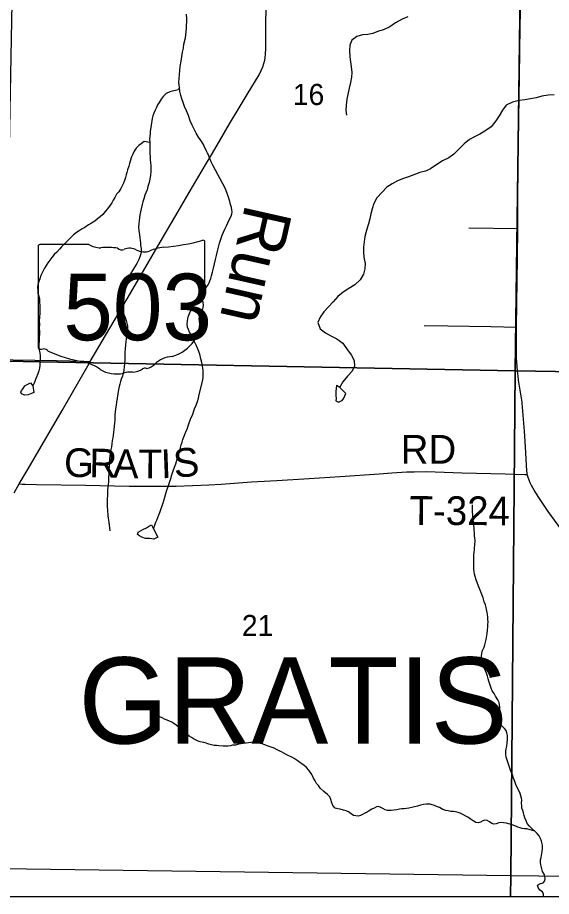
# Model space of a CAD drawing. Extents: x 0 to 34, y 0 to 22.
# Drawn here: x 5.468 to 6.524, y 14.1 to 15.838 of the extents above; entities that cross this region are included whole.
import ezdxf

# ---------------------------------------------------------------- set-up
doc = ezdxf.new("R2010")
doc.units = 0
for name, color, linetype in [('GM_X_Corporation', 7, 'Continuous'), ('GM_X_Minor_River', 7, 'Continuous'), ('GM_X_Minor_River_Text', 7, 'Continuous'), ('GM_X_Section_Text', 7, 'Continuous'), ('GM_X_State_Location', 7, 'Continuous'), ('GM_X_State_Route', 7, 'Continuous'), ('GM_X_State_Shield', 7, 'Continuous'), ('GM_X_Township_Road', 7, 'Continuous'), ('GM_X_Township_Road_Text', 7, 'Continuous'), ('GM_X_Township_Text', 7, 'Continuous'), ('SH_Data', 7, 'Continuous')]:
    doc.layers.add(name, color=color, linetype=linetype)

msp = doc.modelspace()

# ---------------------------------------------------------------- linework, layer by layer
at = {"layer": 'GM_X_Corporation'}
msp.add_lwpolyline([(3.4754, 17.1134), (3.4672, 16.2781), (3.4601, 16.0804), (3.4533, 15.0461), (3.4516, 14.7743), (3.448, 14.3179), (3.4463, 14.1), (8.9, 14.1)], dxfattribs=at)
for points in [[(5.4651, 16.258), (6.4674, 16.2404), (6.4527, 15.1394), (5.4447, 15.1591)], [(6.4674, 16.2404), (7.4675, 16.2282), (7.4535, 15.1233), (6.4527, 15.1394)], [(5.4447, 15.1591), (6.4527, 15.1394), (6.4438, 14.1407), (5.4377, 14.1543)], [(6.4527, 15.1394), (7.4535, 15.1233), (7.4459, 14.1288), (6.4438, 14.1407)], [(5.4372, 14.1), (6.4436, 14.1), (6.4438, 14.1407), (5.4377, 14.1543)], [(6.4436, 14.1), (7.4457, 14.1), (7.4459, 14.1288), (6.4438, 14.1407)]]:
    msp.add_lwpolyline(points, close=True, dxfattribs=at)
at = {"layer": 'GM_X_Minor_River'}
for points in [[(5.8826, 15.4922), (5.8787, 15.5011), (5.8647, 15.5277), (5.8597, 15.5366), (5.855, 15.5451), (5.8511, 15.5532), (5.8479, 15.5609), (5.8458, 15.5666), (5.8441, 15.5701), (5.8426, 15.5728), (5.8412, 15.5759), (5.8391, 15.5809), (5.8359, 15.5871), (5.8315, 15.5948), (5.8265, 15.6022), (5.8218, 15.6099), (5.8175, 15.6176), (5.8135, 15.6254), (5.8096, 15.6342), (5.8062, 15.6446), (5.8023, 15.6542), (5.7988, 15.6623), (5.796, 15.6703), (5.7936, 15.6776), (5.7911, 15.6845), (5.7895, 15.6922), (5.7886, 15.7006), (5.7877, 15.7101), (5.7898, 15.7416), (5.7917, 15.7521), (5.7935, 15.7612), (5.7949, 15.7703), (5.7963, 15.7782), (5.7976, 15.7858), (5.8003, 15.7986), (5.8012, 15.8046), (5.8024, 15.8168), (5.8026, 15.8232), (5.8031, 15.8293), (5.8029, 15.835), (5.8025, 15.8449)], [(6.2403, 15.8402), (6.2292, 15.8356), (6.2157, 15.828), (6.2045, 15.82), (6.1922, 15.8142), (6.1822, 15.8115), (6.1711, 15.8069), (6.1612, 15.8052), (6.1505, 15.804), (6.1394, 15.8013), (6.1294, 15.794), (6.1253, 15.7838), (6.1246, 15.7732), (6.1254, 15.761), (6.127, 15.7507), (6.1282, 15.7408), (6.1294, 15.7301), (6.1288, 15.7203), (6.1266, 15.7101), (6.124, 15.6987), (6.1196, 15.6768), (6.1185, 15.6655), (6.1178, 15.6556), (6.1187, 15.6457)], [(5.7886, 15.7006), (5.7862, 15.6957), (5.7805, 15.6944), (5.7744, 15.6926), (5.7694, 15.6913), (5.7621, 15.6884), (5.7562, 15.6825), (5.7527, 15.6773), (5.7487, 15.6706), (5.7455, 15.6657), (5.7431, 15.6605), (5.7407, 15.6556), (5.7382, 15.6492), (5.7362, 15.6439), (5.7349, 15.6387), (5.7326, 15.6254), (5.7308, 15.6133), (5.7306, 15.6084), (5.7296, 15.5985), (5.7298, 15.5913), (5.73, 15.586), (5.7298, 15.581), (5.7301, 15.5757), (5.7299, 15.5693), (5.7305, 15.5635), (5.7307, 15.5575), (5.7313, 15.5514), (5.7319, 15.546), (5.7321, 15.5407), (5.732, 15.535), (5.7313, 15.5259), (5.7287, 15.5123), (5.7262, 15.5044), (5.7245, 15.498), (5.7224, 15.492), (5.7203, 15.4871), (5.7179, 15.4796), (5.7162, 15.4739), (5.7149, 15.469), (5.7131, 15.4603), (5.7105, 15.4482), (5.7096, 15.4422), (5.7087, 15.4361), (5.7081, 15.4308), (5.7079, 15.4236), (5.7081, 15.4175), (5.7094, 15.4087), (5.71, 15.4026), (5.7106, 15.3977), (5.7116, 15.3927), (5.7118, 15.3874), (5.7132, 15.3816), (5.713, 15.376), (5.7121, 15.371), (5.7104, 15.3654), (5.7084, 15.3597), (5.7044, 15.3523), (5.7008, 15.3467), (5.6976, 15.3414), (5.692, 15.3317), (5.6884, 15.3257), (5.6856, 15.3186), (5.6839, 15.3137), (5.6826, 15.3069), (5.6813, 15.3005), (5.6804, 15.2956), (5.6783, 15.2892), (5.6766, 15.2835), (5.675, 15.2782), (5.6744, 15.2729), (5.6739, 15.2669), (5.6745, 15.2611), (5.6759, 15.2562), (5.6787, 15.2508), (5.6812, 15.2454), (5.6833, 15.2389), (5.6847, 15.2339), (5.6857, 15.2285), (5.6859, 15.2213), (5.6853, 15.2149), (5.6843, 15.2077), (5.6831, 15.2028), (5.6825, 15.1978)], [(6.53, 15.6854), (6.5178, 15.685), (6.5056, 15.6831), (6.4938, 15.68), (6.4827, 15.678), (6.4716, 15.6757), (6.4602, 15.6741), (6.4472, 15.671), (6.4349, 15.6653), (6.4274, 15.6552), (6.4207, 15.6444), (6.4143, 15.6343), (6.4053, 15.6224), (6.3929, 15.6137), (6.3828, 15.6079), (6.3721, 15.6025), (6.3621, 15.5974), (6.3519, 15.589), (6.341, 15.5779), (6.3313, 15.5683), (6.3212, 15.5613), (6.3089, 15.5548), (6.2977, 15.5476), (6.2853, 15.5395), (6.2753, 15.5349), (6.2638, 15.5318), (6.2523, 15.5276), (6.2419, 15.5233), (6.232, 15.5202), (6.2201, 15.5152), (6.2093, 15.5098), (6.1989, 15.5032), (6.1895, 15.4929), (6.1793, 15.4821)], [(5.7298, 15.5913), (5.7188, 15.5931), (5.713, 15.5884), (5.708, 15.5851), (5.7033, 15.5799), (5.6993, 15.5743), (5.6961, 15.5683), (5.694, 15.5627), (5.6911, 15.5544), (5.6895, 15.5495), (5.6882, 15.5446), (5.6861, 15.5374), (5.6848, 15.5322), (5.6835, 15.5273), (5.6819, 15.5224), (5.6798, 15.5163), (5.6778, 15.5107), (5.6753, 15.5055), (5.6725, 15.5002), (5.6689, 15.4939), (5.6642, 15.489), (5.6606, 15.4823), (5.6575, 15.4775), (5.6547, 15.4722), (5.6515, 15.4674), (5.646, 15.4603), (5.6416, 15.4547), (5.6369, 15.4488), (5.6315, 15.4444), (5.6264, 15.4403), (5.621, 15.4359), (5.6144, 15.4319), (5.609, 15.4283), (5.6013, 15.4232), (5.5959, 15.4207), (5.5905, 15.4163), (5.5851, 15.413), (5.5792, 15.4086), (5.5738, 15.4031), (5.5664, 15.3964), (5.5609, 15.3905), (5.5551, 15.385), (5.5511, 15.3801), (5.5464, 15.3746), (5.541, 15.3698), (5.5359, 15.3639), (5.5323, 15.3583), (5.5284, 15.3534), (5.5248, 15.3478), (5.522, 15.343), (5.518, 15.3347)], [(5.7374, 14.8272), (5.738, 14.8288), (5.7397, 14.8341), (5.7417, 14.8401), (5.7438, 14.8442), (5.7479, 14.8547), (5.7495, 14.8596), (5.7516, 14.8656), (5.7541, 14.8724), (5.7562, 14.8788), (5.7587, 14.8852), (5.7633, 14.9017), (5.7663, 14.9111), (5.7692, 14.919), (5.7717, 14.9265), (5.7738, 14.9341), (5.7763, 14.942), (5.7788, 14.9491), (5.7813, 14.9555), (5.7847, 14.9676), (5.7868, 14.9739), (5.7881, 14.9792), (5.7897, 14.9837), (5.7906, 14.9883), (5.7919, 14.9932), (5.794, 14.9984), (5.7956, 15.0041), (5.7977, 15.0101), (5.8002, 15.0157), (5.8043, 15.0262), (5.8059, 15.0311), (5.808, 15.0367), (5.8121, 15.0472), (5.8142, 15.0521), (5.8187, 15.0645), (5.8216, 15.0717), (5.8241, 15.0788), (5.8262, 15.0859), (5.8279, 15.0931), (5.8327, 15.1131), (5.834, 15.1195), (5.8354, 15.1263), (5.8356, 15.1335), (5.8355, 15.1411), (5.8345, 15.1487), (5.8329, 15.156), (5.8312, 15.1637), (5.8288, 15.1725), (5.8257, 15.1809), (5.8225, 15.189), (5.8193, 15.1959), (5.8165, 15.2013), (5.8115, 15.2114), (5.8086, 15.216), (5.8065, 15.2214), (5.8047, 15.226), (5.8041, 15.2317), (5.8047, 15.2385), (5.8061, 15.2465), (5.8086, 15.2532), (5.811, 15.2589), (5.8139, 15.2649), (5.8171, 15.2705), (5.8206, 15.2757), (5.8242, 15.2813), (5.8282, 15.2861), (5.8321, 15.2901), (5.8352, 15.2942), (5.8384, 15.2987), (5.8416, 15.3043), (5.8452, 15.3095), (5.8472, 15.314), (5.8488, 15.3177), (5.8505, 15.3222), (5.8522, 15.3279), (5.8539, 15.3347), (5.856, 15.3426), (5.8582, 15.3513), (5.86, 15.3596), (5.8621, 15.3679), (5.8639, 15.3762), (5.8681, 15.392), (5.8703, 15.4003), (5.8732, 15.4078), (5.876, 15.4141), (5.8785, 15.4202), (5.8817, 15.4265), (5.8845, 15.4325), (5.8878, 15.4396), (5.891, 15.4456), (5.8923, 15.4505), (5.8928, 15.4539), (5.8925, 15.4581), (5.8915, 15.4627), (5.8898, 15.4684), (5.8881, 15.4749), (5.8857, 15.4834), (5.8826, 15.4922)], [(6.1793, 15.4821), (6.1729, 15.4705), (6.1696, 15.4604), (6.167, 15.4505), (6.1652, 15.4403), (6.1627, 15.4305), (6.1593, 15.4196), (6.1555, 15.4057), (6.1537, 15.3947), (6.1523, 15.3845), (6.1524, 15.3746), (6.1536, 15.3643), (6.1559, 15.3521), (6.1552, 15.3411), (6.1526, 15.3309), (6.1462, 15.3197), (6.1357, 15.3101), (6.1234, 15.3024), (6.1122, 15.2952), (6.1017, 15.2867), (6.0927, 15.2763), (6.0833, 15.2663), (6.0743, 15.2563), (6.0668, 15.2459), (6.0623, 15.2354), (6.0672, 15.2227), (6.0772, 15.2148), (6.0881, 15.2092), (6.0997, 15.2028), (6.1116, 15.1941), (6.1203, 15.1821), (6.1287, 15.1708), (6.1341, 15.1596), (6.135, 15.149), (6.1305, 15.1392), (6.1211, 15.1288), (6.1117, 15.1177), (6.1061, 15.1076), (6.1058, 15.1067)], [(5.518, 15.3347), (5.5144, 15.3284), (5.5123, 15.3216), (5.5102, 15.3163), (5.5085, 15.3103), (5.5076, 15.305), (5.5082, 15.2985), (5.5084, 15.2932), (5.5102, 15.2874), (5.5115, 15.2817), (5.5121, 15.2756), (5.5127, 15.2691), (5.5128, 15.2608), (5.5123, 15.2543), (5.5116, 15.2452), (5.5114, 15.2388), (5.5116, 15.2315), (5.5114, 15.2247), (5.5116, 15.2163), (5.5108, 15.1883), (5.5113, 15.1803), (5.5123, 15.1753), (5.5129, 15.1696), (5.513, 15.1616), (5.5125, 15.1563), (5.5124, 15.1506), (5.5118, 15.1449), (5.5105, 15.1396), (5.5088, 15.1336), (5.5052, 15.1261), (5.5035, 15.1208), (5.5003, 15.1137), (5.4984, 15.1099)], [(5.6825, 15.1978), (5.6819, 15.1903), (5.6814, 15.183), (5.6808, 15.1766), (5.6806, 15.1698), (5.6804, 15.1618), (5.6798, 15.1535), (5.6792, 15.1478), (5.6783, 15.141), (5.677, 15.1349), (5.6757, 15.1293), (5.6736, 15.1232), (5.6723, 15.1183), (5.6707, 15.1134), (5.6694, 15.1085), (5.6681, 15.1029), (5.6672, 15.098), (5.6662, 15.0911), (5.6653, 15.0851), (5.664, 15.0783), (5.6634, 15.0715), (5.6621, 15.0647), (5.6615, 15.0586), (5.661, 15.0529), (5.6607, 15.0419), (5.6601, 15.0366), (5.6596, 15.0298), (5.659, 15.0237), (5.6585, 15.0184), (5.6572, 15.0124), (5.6566, 15.0074), (5.6557, 15.0018), (5.6548, 14.9953), (5.6539, 14.9896), (5.6529, 14.984), (5.6516, 14.976), (5.6511, 14.9711), (5.6501, 14.9647), (5.6495, 14.9563), (5.6493, 14.9499), (5.6488, 14.9446), (5.6481, 14.9199), (5.6476, 14.915), (5.6465, 14.9036), (5.6463, 14.8983), (5.6462, 14.893), (5.6456, 14.8865), (5.6455, 14.8812), (5.6457, 14.8759), (5.6459, 14.8698), (5.6465, 14.8645), (5.647, 14.853), (5.6476, 14.8481), (5.6489, 14.8401), (5.6495, 14.8344), (5.6501, 14.8294), (5.6507, 14.8229)], [(5.4984, 15.1099), (5.5007, 15.0969), (5.496, 15.0947), (5.4895, 15.0922), (5.4827, 15.0917), (5.4778, 15.0934), (5.4763, 15.0942), (5.4749, 15.0972), (5.4765, 15.1006), (5.4796, 15.1047), (5.4825, 15.1103), (5.4871, 15.1125)], [(5.4871, 15.1125), (5.4939, 15.1162), (5.4984, 15.1099)], [(6.1058, 15.1067), (6.0995, 15.1108), (6.0976, 15.0991), (6.0981, 15.0911), (6.0983, 15.0847), (6.0982, 15.0801), (6.103, 15.0777), (6.1073, 15.0795)], [(6.1073, 15.0795), (6.1107, 15.0813), (6.1139, 15.0857), (6.118, 15.0947), (6.1058, 15.1067)], [(6.4217, 14.4787), (6.4207, 14.4833), (6.4186, 14.4887), (6.414, 14.4961), (6.4108, 14.5015), (6.4073, 14.5069), (6.4052, 14.5119), (6.4025, 14.5196), (6.4004, 14.5261), (6.3991, 14.5307), (6.3981, 14.5357), (6.3957, 14.5418), (6.394, 14.5461), (6.3909, 14.5534), (6.3888, 14.5588), (6.3872, 14.5649), (6.3859, 14.571), (6.3861, 14.576), (6.3866, 14.5801), (6.3875, 14.5851), (6.3892, 14.5892), (6.3912, 14.5933), (6.3929, 14.5978), (6.3942, 14.6031), (6.3951, 14.608), (6.3956, 14.6122), (6.397, 14.6202), (6.3977, 14.6274), (6.3982, 14.6323), (6.3988, 14.638), (6.399, 14.6429), (6.3988, 14.6479), (6.3986, 14.6521), (6.398, 14.6574), (6.3974, 14.6616), (6.3961, 14.6673), (6.3955, 14.6715), (6.3938, 14.6765), (6.3914, 14.6827), (6.3891, 14.6907), (6.3867, 14.6973), (6.3846, 14.7027), (6.3822, 14.7092), (6.3801, 14.7134), (6.3753, 14.7265), (6.3733, 14.7326), (6.3719, 14.7376), (6.3714, 14.743), (6.3708, 14.7472), (6.3706, 14.7533), (6.3708, 14.7578), (6.3706, 14.7631), (6.3711, 14.7757), (6.3716, 14.7802), (6.3722, 14.7855), (6.3723, 14.7901), (6.3728, 14.7943), (6.3732, 14.8045), (6.373, 14.8087), (6.3724, 14.8133), (6.3719, 14.819), (6.3717, 14.8243), (6.371, 14.8369), (6.37, 14.8415), (6.3698, 14.8457), (6.3687, 14.8556), (6.3681, 14.8602), (6.3679, 14.8651), (6.3682, 14.8746)], [(5.7374, 14.8272), (5.7456, 14.8108), (5.7382, 14.8068), (5.7303, 14.8082), (5.7212, 14.8077), (5.7145, 14.8109), (5.7096, 14.8134), (5.7059, 14.8161), (5.7068, 14.8203), (5.716, 14.8257), (5.7237, 14.8289), (5.7296, 14.8333)], [(5.7296, 14.8333), (5.7333, 14.8351)], [(5.7333, 14.8351), (5.7374, 14.8272)], [(6.5084, 14.1), (6.5084, 14.1001), (6.5089, 14.1043), (6.5065, 14.1089), (6.5013, 14.1125), (6.4978, 14.1175), (6.4968, 14.1225), (6.5026, 14.1257), (6.5079, 14.1267), (6.511, 14.1308), (6.5116, 14.1354), (6.511, 14.1396), (6.5096, 14.1438), (6.5068, 14.1496), (6.5051, 14.1546), (6.5031, 14.1626), (6.5026, 14.1672), (6.5027, 14.1721), (6.5037, 14.1771), (6.5054, 14.185), (6.5063, 14.1891), (6.5069, 14.1948), (6.5067, 14.1998), (6.5061, 14.204), (6.5048, 14.2093), (6.5027, 14.2144), (6.5003, 14.2197), (6.4963, 14.2244), (6.4912, 14.2291), (6.4854, 14.2346), (6.4807, 14.2393), (6.4764, 14.2444), (6.4743, 14.2498), (6.4719, 14.2552), (6.4702, 14.2602), (6.4689, 14.2651), (6.4675, 14.2698), (6.4658, 14.2744), (6.4656, 14.2789), (6.4654, 14.2843), (6.4656, 14.2903), (6.465, 14.2945), (6.4641, 14.2991), (6.4624, 14.3037), (6.4596, 14.3095), (6.4564, 14.3157), (6.4536, 14.3211), (6.4516, 14.3273), (6.4495, 14.3342), (6.4478, 14.3392), (6.4454, 14.3449), (6.4433, 14.3499), (6.4406, 14.3576), (6.4386, 14.3638), (6.4362, 14.3714), (6.4345, 14.3757), (6.4339, 14.3806), (6.4342, 14.3875), (6.4351, 14.392), (6.436, 14.3973), (6.437, 14.4041), (6.4373, 14.4113), (6.4371, 14.4182), (6.4362, 14.4235), (6.4345, 14.4282), (6.4316, 14.4324), (6.4276, 14.436), (6.4233, 14.4403), (6.4208, 14.4457), (6.4195, 14.4503), (6.4189, 14.4545), (6.4195, 14.4598), (6.4212, 14.465), (6.4221, 14.4696), (6.4223, 14.4745), (6.4217, 14.4787)], [(5.9948, 14.3834), (5.9907, 14.3858), (5.9859, 14.3878), (5.9819, 14.3902), (5.976, 14.3934), (5.9663, 14.3968), (5.9589, 14.3993), (5.9544, 14.4009), (5.9492, 14.4026), (5.944, 14.4039), (5.9395, 14.4044), (5.9347, 14.4049), (5.9298, 14.4047), (5.9252, 14.404), (5.9203, 14.4034), (5.9147, 14.4024), (5.9101, 14.4018), (5.9037, 14.4005), (5.8995, 14.3995), (5.8935, 14.3989), (5.8893, 14.3982), (5.8844, 14.3972), (5.8792, 14.397), (5.875, 14.3971), (5.8664, 14.3977), (5.8619, 14.3983), (5.857, 14.3988), (5.8466, 14.4014), (5.8414, 14.4034), (5.8366, 14.4043), (5.8299, 14.406), (5.8258, 14.4073), (5.8206, 14.4097), (5.8165, 14.4114), (5.8125, 14.4141), (5.8081, 14.4173), (5.8037, 14.4201), (5.799, 14.424), (5.7909, 14.4311), (5.7862, 14.4354), (5.7818, 14.439), (5.7778, 14.4418), (5.7734, 14.4445), (5.7686, 14.447), (5.7641, 14.4486), (5.7593, 14.4507), (5.7542, 14.4531), (5.7497, 14.4551), (5.7449, 14.4564)], [(6.4912, 14.2291), (6.4756, 14.2338), (6.4711, 14.2335), (6.4666, 14.2344), (6.4622, 14.2357), (6.4577, 14.2373), (6.4536, 14.239), (6.4447, 14.2423), (6.4395, 14.2436), (6.4354, 14.2448), (6.4298, 14.2457), (6.425, 14.2459), (6.4201, 14.2453), (6.4151, 14.2439), (6.4106, 14.2429), (6.4065, 14.2441), (6.4021, 14.2473), (6.3973, 14.2505), (6.3928, 14.2506), (6.3886, 14.2492), (6.384, 14.2471), (6.3791, 14.2453), (6.3746, 14.2462), (6.3695, 14.2494), (6.3636, 14.2533), (6.3592, 14.2565), (6.3548, 14.2585), (6.3489, 14.2621), (6.3441, 14.2646), (6.34, 14.2658), (6.3348, 14.2671), (6.3303, 14.268), (6.3254, 14.2681), (6.3198, 14.2691), (6.3157, 14.2699), (6.3098, 14.272), (6.3028, 14.2756), (6.2972, 14.2781), (6.2932, 14.2797), (6.2887, 14.281), (6.2846, 14.2822), (6.2805, 14.2827), (6.2763, 14.2825), (6.2711, 14.2819), (6.2654, 14.2805), (6.2593, 14.2788), (6.2536, 14.2774), (6.2483, 14.2761), (6.2426, 14.2747), (6.2332, 14.2735), (6.2287, 14.2732), (6.2238, 14.2726), (6.2185, 14.2712), (6.2124, 14.2703), (6.2075, 14.27), (6.2, 14.2698), (6.1955, 14.2711), (6.1907, 14.2739), (6.1867, 14.2759), (6.1826, 14.2776), (6.1781, 14.2773), (6.1739, 14.2748), (6.1689, 14.2723), (6.1639, 14.2694), (6.1597, 14.2668), (6.1555, 14.2647), (6.1509, 14.2618), (6.1467, 14.26), (6.1421, 14.259), (6.1376, 14.2591), (6.1328, 14.2604), (6.128, 14.2636), (6.1229, 14.2671), (6.1181, 14.2695), (6.1132, 14.2708), (6.1065, 14.2725), (6.1021, 14.2734), (6.0965, 14.2747), (6.0921, 14.2798), (6.0897, 14.2848), (6.0881, 14.2917), (6.086, 14.2967), (6.0817, 14.3018), (6.0743, 14.3073), (6.0671, 14.3144), (6.0635, 14.3194), (6.0599, 14.3237), (6.0571, 14.3287), (6.0535, 14.3342), (6.0504, 14.3411), (6.0447, 14.3496), (6.0396, 14.3551), (6.0352, 14.359), (6.0309, 14.3626), (6.0268, 14.365), (6.0213, 14.3686), (6.0158, 14.3729), (6.0107, 14.3757), (6.0051, 14.3782), (5.9999, 14.3806), (5.9948, 14.3834)]]:
    msp.add_lwpolyline(points, dxfattribs=at)
at = {"layer": 'GM_X_State_Route'}
msp.add_lwpolyline([(5.4619, 14.8983), (5.4719, 14.9162), (5.4893, 14.9457), (5.5564, 15.0613), (5.6099, 15.1544), (5.6121, 15.158), (5.6917, 15.2936), (5.7549, 15.402), (5.7859, 15.4551), (5.808, 15.4926), (5.8422, 15.5502), (5.8495, 15.5624), (5.8705, 15.5984), (5.8879, 15.6285), (5.9064, 15.6601), (5.9223, 15.686), (5.9461, 15.7254), (5.9504, 15.7337), (5.9536, 15.7412), (5.9558, 15.7478), (5.9573, 15.7542), (5.9581, 15.7588), (5.9589, 15.7669), (5.9593, 15.7769), (5.9595, 15.8049), (5.9609, 15.949)], dxfattribs=at)
at = {"layer": 'GM_X_State_Shield'}
for p, q in [((5.5094, 15.3861), (5.5094, 15.186)), ((5.6092, 15.3896), (5.5127, 15.3896)), ((5.839, 15.2898), (5.839, 15.3945)), ((5.839, 15.2899), (5.839, 15.2898))]:
    msp.add_line(p, q, dxfattribs=at)
for centre, major_axis, start_param, end_param in [((5.5132, 15.3865), (0.00382, 0), 1.712693, 3.28349), ((5.6322, 15.4128), (0.037, 0), 4.042523, 4.731795), ((5.7216, 15.6624), (0.3495, 0), 4.814394, 5.042369), ((5.8354, 15.395), (0.00367, 0), 6.141152, 7.989035), ((5.6445, 15.2772), (0.133, 0), 1.404758, 1.657858), ((5.6746, 15.3876), (0.0107, 0), 3.836095, 5.185415), ((5.6903, 15.3645), (0.0222, 0), 0.950623, 2.079405), ((5.719, 15.3962), (0.0267, 0), 4.081561, 5.145723), ((5.7662, 15.3284), (0.0703, 0), 1.699011, 2.107814), ((5.8382, 15.2821), (0.00568, 0), 1.883978, 3.671073), ((5.8351, 15.2894), (0.00393, 0), 5.05454, 6.418171), ((5.802, 15.2689), (0.0341, 0), 5.934695, 6.695948), ((5.8522, 15.246), (0.0248, 0), 2.387724, 3.262537), ((5.7412, 15.2327), (0.0874, 0), 5.101752, 6.440018), ((5.5132, 15.1856), (0.00385, 0), 3.00124, 4.508301), ((5.5138, 15.206), (0.0294, 0), 4.665946, 4.897461), ((5.5198, 15.1745), (0.0106, 0), 0.519207, 1.627899), ((5.6537, 15.3543), (0.2524, 0), 4.195997, 4.488961), ((5.778, 15.1298), (0.0479, 0), 1.647645, 2.488434), ((5.5784, 15.0961), (0.079, 0), 0.823519, 1.323587), ((5.6638, 15.1735), (0.0501, 0), 4.026481, 4.996735), ((5.6964, 15.1585), (0.0267, 0), 4.691044, 5.507374), ((5.7206, 15.1391), (0.00752, 0), 1.147584, 2.315152), ((5.7174, 15.1666), (0.0282, 0), 4.937069, 5.64225), ((5.6928, 15.1043), (0.0412, 0), 1.495662, 1.94098)]:
    msp.add_ellipse(centre, major_axis=major_axis, ratio=0.8, start_param=start_param, end_param=end_param, dxfattribs=at)
at = {"layer": 'GM_X_Township_Road'}
msp.add_line((6.3607, 15.4225), (6.4577, 15.4212), dxfattribs=at)
for points in [[(6.5501, 14.8172), (6.5181, 14.8615), (6.4992, 14.8892), (6.49, 14.9039), (6.4851, 14.9126), (6.4824, 14.9182), (6.4801, 14.9233), (6.4782, 14.9285), (6.4769, 14.9333), (6.4766, 14.9348), (6.4761, 14.9376), (6.4757, 14.9413), (6.4731, 14.9896), (6.4713, 15.0205), (6.4665, 15.0756), (6.4661, 15.078), (6.4607, 15.113), (6.4594, 15.1209), (6.4582, 15.1292), (6.4571, 15.1396), (6.4556, 15.1568), (6.4554, 15.1643), (6.4554, 15.1829), (6.4554, 15.2262), (6.4558, 15.2719), (6.4571, 15.3626), (6.4577, 15.4212), (6.458, 15.4785), (6.4582, 15.5431), (6.46, 15.6378), (6.4614, 15.7229), (6.4624, 15.8204), (6.4655, 15.9682)], [(6.2727, 15.2293), (6.3192, 15.2288), (6.4042, 15.2272), (6.4554, 15.2262)], [(4.8444, 15.1679), (4.8817, 15.1677), (4.9717, 15.1661), (5.045, 15.1653), (5.1263, 15.1642), (5.1697, 15.164), (5.2275, 15.164), (5.307, 15.1633), (5.4598, 15.1613), (5.5453, 15.1598), (5.5993, 15.1587), (5.6061, 15.1583), (5.6121, 15.158)], [(5.4719, 14.9162), (5.4777, 14.9157), (5.4832, 14.9153), (5.5056, 14.9147), (5.6031, 14.9133), (5.6894, 14.9118), (5.7241, 14.9117), (5.7819, 14.9116), (5.8464, 14.914), (5.8711, 14.9152), (5.9308, 14.9198), (5.9809, 14.9226), (6.0454, 14.9265), (6.1067, 14.9305), (6.1836, 14.936), (6.2089, 14.9382), (6.2383, 14.9399), (6.253, 14.9399), (6.2763, 14.9404), (6.3477, 14.9377), (6.4325, 14.9359), (6.4715, 14.9349), (6.4766, 14.9348)]]:
    msp.add_lwpolyline(points, dxfattribs=at)
at = {"layer": 'SH_Data'}
msp.add_line((2.1, 14.1), (8.9, 14.1), dxfattribs=at)
msp.add_line((2.1, 14.1), (8.9, 14.1), dxfattribs=at)
msp.add_line((2.1, 14.1), (8.9, 14.1), dxfattribs=at)

# ---------------------------------------------------------------- texts
at = {"layer": 'GM_X_Minor_River_Text'}
msp.add_text('Run', height=0.09466, rotation=257.2923, dxfattribs=at).set_placement((5.9195, 15.4721))
at = {"layer": 'GM_X_Section_Text'}
for s, p in [('16', (6.0128, 15.6654)), ('21', (5.912, 14.6149))]:
    msp.add_text(s, height=0.04186, rotation=0, dxfattribs=at).set_placement(p)
at = {"layer": 'GM_X_State_Location'}
for s in ['s', 'r']:
    msp.add_text(s, height=0.000189, dxfattribs=at).set_placement((5.6705, 15.2728))
msp.add_text('503', height=0.000189, rotation=0, dxfattribs=at).set_placement((5.6037, 15.259))
at = {"layer": 'GM_X_State_Shield'}
msp.add_text('503', height=0.13184, dxfattribs=at).set_placement((5.5589, 15.2001))
at = {"layer": 'GM_X_Township_Road_Text'}
for s, height, rotation, p in [('RD', 0.05682, 0, (6.2262, 14.956)), ('G', 0.0568, 358.8306, (5.5599, 14.9302)), ('R', 0.0568, 358.829, (5.6099, 14.9292)), ('S', 0.0568, 4.9908, (5.7791, 14.9281)), ('A', 0.0568, 358.8364, (5.6566, 14.9282)), ('T', 0.0568, 359.7279, (5.7076, 14.9272)), ('I', 0.0568, 2.1244, (5.7527, 14.927)), ('T-324', 0.05682, 359.7186, (6.2436, 14.8351))]:
    msp.add_text(s, height=height, rotation=rotation, dxfattribs=at).set_placement(p)
at = {"layer": 'GM_X_Township_Text'}
msp.add_text('GRATIS', height=0.17045, rotation=0, dxfattribs=at).set_placement((5.589, 14.4024))

doc.saveas('drawing.dxf')
